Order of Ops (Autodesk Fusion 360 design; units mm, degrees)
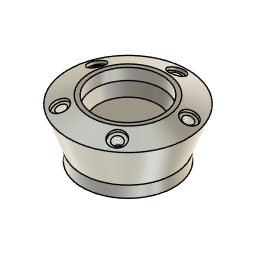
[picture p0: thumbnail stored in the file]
sketch "Sketch1" plane through (0, 0, 0) normal (1, 0, 0) x axis (0, 1, 0)
  line L1 (0, 63.5) -> (0, 0)
  line L2 (42.2596, 63.5) -> (0, 63.5)
  line L3 (66.1278, 54.8127) -> (42.2596, 63.5)
  line L4 (50.8, 12.7) -> (66.1278, 54.8127)
  line L5 (50.8, 0) -> (50.8, 12.7)
  line L6 (0, 0) -> (50.8, 0)
  line L7 (37.6371, 50.8) -> (37.6371, 63.5)
  line L8 (33.0147, 38.1) -> (37.6371, 50.8)
  line L9 (0, 38.1) -> (33.0147, 38.1)
  line L10 (42.2596, 63.5) -> (37.6371, 50.8)
  point P1 (0, 0)
  point P2 (0, 0)
  point P8 (0, 0)
  point P9 (37.6371, 63.5)
  point P12 (0, 38.1)
  point P6 (50.8, 12.7)
  point P7 (50.8, 0)
  point P4 (42.2596, 63.5)
  point P5 (66.1278, 54.8127)
  point P3 (0, 63.5)
  point P10 (37.6371, 50.8)
  coincident P1 P2
  vertical L1
  perpendicular L1 L2
  perpendicular L2 L5
  coincident P1 P8
  horizontal L6
  perpendicular L3 L4
  coincident L2 P9
  perpendicular L2 L7
  coincident L1 P12
  perpendicular L1 L9
  collinear L8 L10
  parallel L4 L10
  dimension "d1" = 101.6
  dimension "d2" distance P6 P7 = 12.7
  dimension "d3" angle L4 L5 = 20
  dimension "d4" distance P4 P5 = 25.4
  dimension "d5" distance P2 P3 = 63.5
  dimension "d7" distance P9 P10 = 12.7
  dimension "d8" distance L2 L9 = 25.4
revolve "Revolve1" sketch "Sketch1" AlongAngle 360 bodies "Part"
work_plane "WorkPlane1" RotateAngle 0
sketch "Sketch2" plane through (0, 54.1937, 59.1563) normal (0, 0.342, 0.9397) x axis (0, 0.9397, -0.342)
  circle C1 centre (0, 0) radius 8.903
  point P1 (0, 0)
  point P2 (0, 0)
  coincident P1 P2
  dimension "d10" diameter C1 = 17.806
copy_paste_bodies "CopyPasteBodies1"
extrude "Extrude1" cut sketch "Sketch2" against normal blind 3.175
hole "Hole1" HoleDepth 12.7 HoleDiameter 10.6426 TipAngle 118
circular_pattern "C-Pattern1" TotalAngle 360
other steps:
base_feature "Base Feature" bodies "Stock"
thread "Thread1" ThreadOffset 0 ThreadDepth 10.0076
named bodies: "Part", "Stock"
